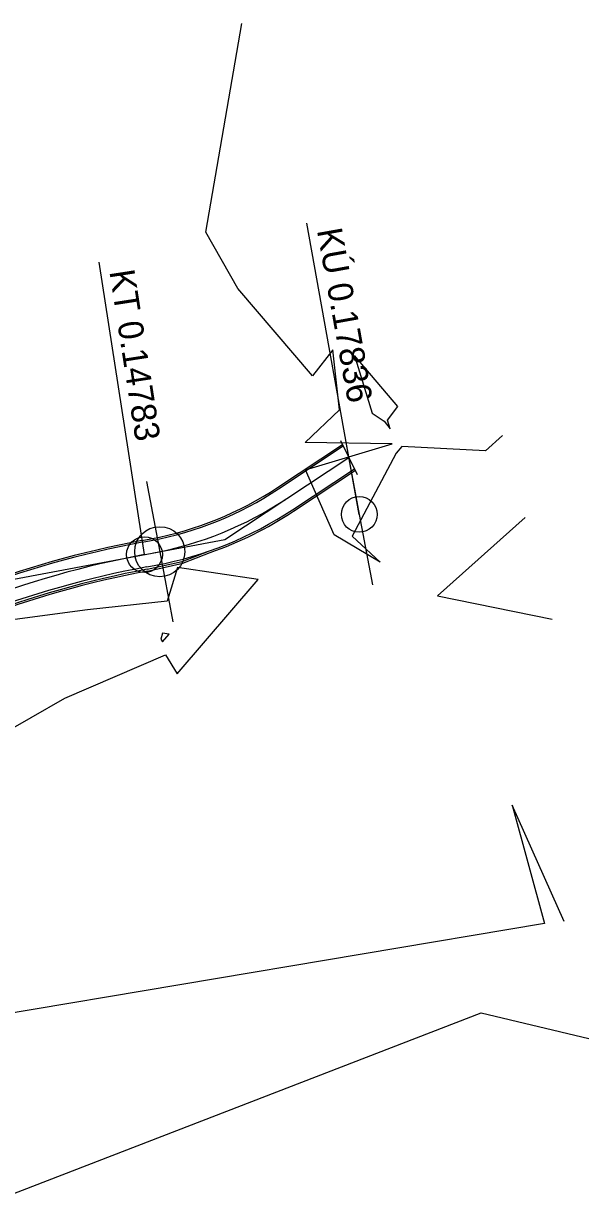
# Model space of a CAD drawing. Extents: x -549394 to -546608, y -1037055 to -1033629.
# Drawn here: x -547298.7 to -547219.7, y -1035265.1 to -1035102.2 of the extents above; entities that cross this region are included whole.
import ezdxf

# ---------------------------------------------------------------- set-up
doc = ezdxf.new("R2010")
doc.units = 0
for name, color, linetype in [('hlavni_vrst', 7, 'Continuous'), ('norm_vrst', 7, 'Continuous'), ('POLYGONY_SITUACE_PO', 7, 'Continuous'), ('u_sirka_1_5m', 7, 'Continuous'), ('x_navrh_C14', 7, 'Continuous'), ('x_osa_C14', 7, 'Continuous'), ('x_popis_oblouky_C14', 7, 'Continuous'), ('x_popis_pricne_rezy_C14', 7, 'Continuous')]:
    doc.layers.add(name, color=color, linetype=linetype)

msp = doc.modelspace()

# ---------------------------------------------------------------- linework, layer by layer
at = {"layer": 'hlavni_vrst'}
for p, q in [((-547228.59, -1035171.26), (-547240.83, -1035182.23)), ((-547277.19, -1035178.24), (-547278.61, -1035182.98)), ((-547265.9, -1035179.96), (-547277.19, -1035178.24)), ((-547277.24, -1035193.14), (-547265.9, -1035179.96)), ((-547240.83, -1035182.23), (-547224.82, -1035185.5)), ((-547278.61, -1035182.98), (-547289.76, -1035184.18)), ((-547289.76, -1035184.18), (-547302.05, -1035185.79)), ((-547292.9, -1035196.54), (-547278.84, -1035190.47)), ((-547278.84, -1035190.47), (-547277.24, -1035193.14)), ((-547317.64, -1035210.67), (-547292.9, -1035196.54)), ((-547230.43, -1035211.49), (-547225.89, -1035228.02)), ((-547223.15, -1035227.75), (-547230.43, -1035211.49)), ((-547225.89, -1035228.02), (-547315.67, -1035243.17)), ((-547315.53, -1035271.79), (-547234.74, -1035240.52)), ((-547234.74, -1035240.52), (-547219.72, -1035244.12))]:
    msp.add_line(p, q, dxfattribs=at)
at = {"layer": 'norm_vrst'}
for p, q in [((-547273.24, -1035131.36), (-547268.2, -1035102.17)), ((-547268.74, -1035139.27), (-547273.24, -1035131.36)), ((-547258.3, -1035151.47), (-547268.74, -1035139.27)), ((-547255.46, -1035147.84), (-547258.3, -1035151.47)), ((-547254.54, -1035156.23), (-547255.46, -1035147.84)), ((-547252.45, -1035148.62), (-547249.96, -1035156.67)), ((-547246.37, -1035155.76), (-547252.45, -1035148.62)), ((-547259.33, -1035160.77), (-547254.54, -1035156.23)), ((-547247.82, -1035157.66), (-547246.37, -1035155.76)), ((-547249.96, -1035156.67), (-547248.28, -1035157.82)), ((-547248.28, -1035157.82), (-547247.47, -1035158.85)), ((-547247.47, -1035158.85), (-547247.82, -1035157.66)), ((-547247.17, -1035160.96), (-547259.33, -1035160.77)), ((-547259.27, -1035164.6), (-547247.17, -1035160.96)), ((-547231.76, -1035159.81), (-547234.13, -1035161.94)), ((-547246.61, -1035162.26), (-547252.78, -1035173.87)), ((-547245.84, -1035161.34), (-547246.61, -1035162.26)), ((-547234.13, -1035161.94), (-547245.84, -1035161.34)), ((-547255.27, -1035173.67), (-547259.27, -1035164.6)), ((-547248.86, -1035177.5), (-547255.27, -1035173.67)), ((-547252.78, -1035173.87), (-547248.86, -1035177.5)), ((-547279.27, -1035187.44), (-547279.52, -1035188.27)), ((-547279.52, -1035188.27), (-547279.28, -1035188.67)), ((-547279.28, -1035188.67), (-547278.34, -1035187.58)), ((-547278.34, -1035187.58), (-547279.27, -1035187.44))]:
    msp.add_line(p, q, dxfattribs=at)
at = {"layer": 'POLYGONY_SITUACE_PO'}
for centre in [(-547251.78, -1035170.83), (-547281.79, -1035176.45)]:
    msp.add_circle(centre, 2.5, dxfattribs=at)
at = {"layer": 'u_sirka_1_5m'}
msp.add_circle((-547279.66, -1035176.05), 3.5, dxfattribs=at)
at = {"layer": 'x_navrh_C14'}
for p, q in [((-547254.4, -1035160.48), (-547252.07, -1035165.24)), ((-547282.16, -1035174.49), (-547280.89, -1035174.25)), ((-547282.12, -1035174.73), (-547280.85, -1035174.5)), ((-547281.47, -1035178.17), (-547280.2, -1035177.94))]:
    msp.add_line(p, q, dxfattribs=at)
for points in [[(-547263.19, -1035167.06), (-547254.12, -1035161.05)], [(-547263.05, -1035167.27), (-547254.01, -1035161.27)], [(-547261.11, -1035170.19), (-547252.46, -1035164.45)], [(-547260.98, -1035170.4), (-547252.32, -1035164.65)], [(-547281.41, -1035178.51), (-547276.52, -1035177.42), (-547272.69, -1035175.94)], [(-547281.35, -1035178.75), (-547276.45, -1035177.66), (-547272.6, -1035176.17)]]:
    msp.add_lwpolyline(points, dxfattribs=at)
for centre, radius, start, end in [((-547289.73, -1035127.07), 48, 280.6108, 303.5694), ((-547289.73, -1035127.07), 48.25, 280.6108, 303.5694), ((-547289.73, -1035127.07), 51.75, 280.6108, 303.5694), ((-547289.73, -1035127.07), 52, 289.2205, 303.5694), ((-547256.01, -1035314.06), 142, 100.6108, 121.3907), ((-547256.01, -1035314.06), 141.75, 100.6108, 121.3907), ((-547256.01, -1035314.06), 138.25, 100.6108, 121.3907), ((-547256.01, -1035314.06), 137.91, 100.6108, 121.3907), ((-547256.01, -1035314.06), 137.66, 100.609, 121.3924)]:
    msp.add_arc(centre, radius, start, end, dxfattribs=at)
at = {"layer": 'x_osa_C14'}
msp.add_lwpolyline([(-547307.02, -1035181.18), (-547270.54, -1035174.35), (-547253.23, -1035162.86)], dxfattribs=at)
for centre, radius, start, end in [((-547289.73, -1035127.07), 50, 280.6108, 303.5694), ((-547256.01, -1035314.06), 140, 100.6108, 121.3907)]:
    msp.add_arc(centre, radius, start, end, dxfattribs=at)
at = {"layer": 'x_popis_oblouky_C14'}
for points in [[(-547251.78, -1035170.83), (-547259.1, -1035130.11)], [(-547281.79, -1035176.45), (-547288.12, -1035135.57)]]:
    msp.add_lwpolyline(points, dxfattribs=at)
at = {"layer": 'x_popis_pricne_rezy_C14'}
for points in [[(-547253.62, -1035161), (-547251.78, -1035170.83), (-547249.94, -1035180.66)], [(-547281.5, -1035166.23), (-547279.66, -1035176.05), (-547277.82, -1035185.88)]]:
    msp.add_lwpolyline(points, dxfattribs=at)

# ---------------------------------------------------------------- texts
at = {"layer": 'x_popis_oblouky_C14'}
for s, rotation, p in [('KÚ 0.17836', 280.1885, (-547257.7, -1035131.1)), ('KT 0.14783', 278.7995, (-547286.7, -1035136.86))]:
    msp.add_text(s, height=3.5, rotation=rotation, dxfattribs=at).set_placement(p)

doc.saveas('drawing.dxf')
